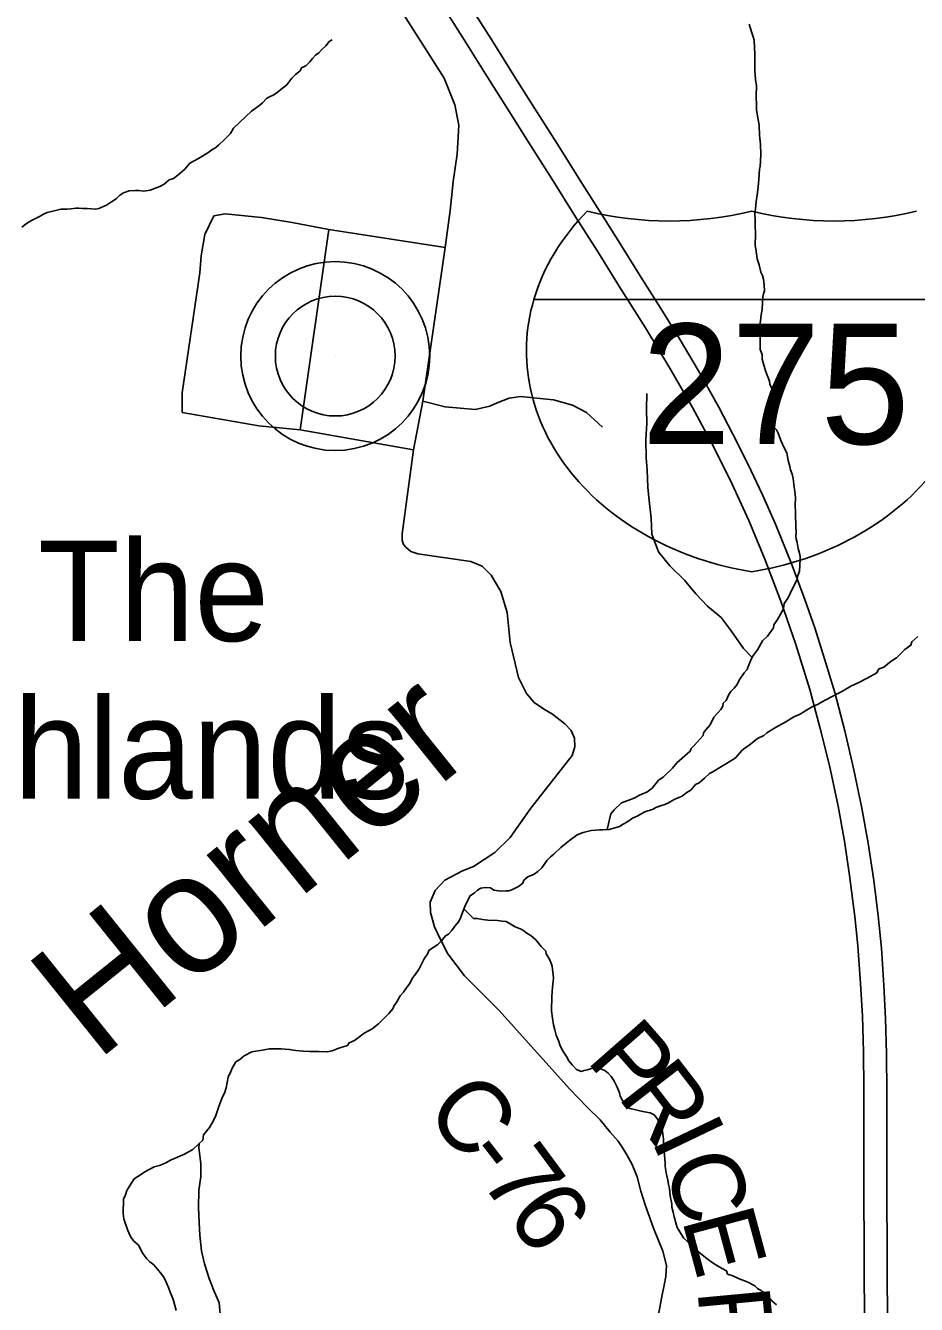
# Model space of a CAD drawing. Extents: x 44.2 to 78.2, y 4.5 to 26.5.
# Drawn here: x 50.361 to 51.062, y 23.779 to 24.786 of the extents above; entities that cross this region are included whole.
import ezdxf

# ---------------------------------------------------------------- set-up
doc = ezdxf.new("R2010")
doc.units = 0
for name, color, linetype in [('GM_X_County_Road', 7, 'Continuous'), ('GM_X_County_Road_Text', 7, 'Continuous'), ('GM_X_Interstate_Location', 7, 'Continuous'), ('GM_X_Interstate_Route', 7, 'Continuous'), ('GM_X_Interstate_Shield', 7, 'Continuous'), ('GM_X_Minor_Lake', 7, 'Continuous'), ('GM_X_Minor_River', 7, 'Continuous'), ('GM_X_Minor_River_Text', 7, 'Continuous'), ('GM_X_Township_Road', 7, 'Continuous'), ('GM_X_Unincorporated', 7, 'Continuous'), ('GM_X_Unincorporated_Location', 7, 'Continuous'), ('GM_X_Unincorporated_Text', 7, 'Continuous')]:
    doc.layers.add(name, color=color, linetype=linetype)

msp = doc.modelspace()

# ---------------------------------------------------------------- linework, layer by layer
at = {"layer": 'GM_X_County_Road'}
for points in [[(50.6961, 24.6507), (50.6974, 24.6636), (50.7006, 24.6852), (50.7018, 24.708), (50.6986, 24.724), (50.6902, 24.7449), (50.6457, 24.8153), (50.6594, 24.8273), (50.6684, 24.8359), (50.6821, 24.8482), (50.6989, 24.8631)], [(50.8591, 23.771), (50.862, 23.7867), (50.8635, 23.7942), (50.8649, 23.8011), (50.8653, 23.8097), (50.8625, 23.8211), (50.8552, 23.8392), (50.8485, 23.8574), (50.8453, 23.8683), (50.8424, 23.8795), (50.8383, 23.8893), (50.8341, 23.8969), (50.8305, 23.9029), (50.8274, 23.9077), (50.8211, 23.9147), (50.8131, 23.9244), (50.8032, 23.9342), (50.789, 23.949), (50.7336, 24.0107), (50.7063, 24.0379), (50.6933, 24.0551), (50.6872, 24.067), (50.6827, 24.0764), (50.6796, 24.0878), (50.6792, 24.096), (50.6832, 24.105), (50.6909, 24.1132), (50.7047, 24.1205), (50.7135, 24.1241), (50.7302, 24.1351), (50.7422, 24.1468), (50.7585, 24.1699), (50.7911, 24.2114), (50.7933, 24.2184), (50.7929, 24.2252), (50.7903, 24.2312), (50.7854, 24.2364), (50.7755, 24.2439), (50.7692, 24.2476), (50.7611, 24.2532), (50.7551, 24.2604), (50.7488, 24.273), (50.7422, 24.3004), (50.7399, 24.3241), (50.735, 24.3407), (50.7274, 24.3536), (50.7203, 24.3607), (50.7112, 24.3644), (50.6695, 24.3704), (50.6641, 24.3721), (50.6602, 24.3755), (50.6583, 24.3778), (50.6573, 24.3808), (50.6573, 24.3862), (50.6662, 24.4523), (50.6734, 24.4905), (50.691, 24.6116), (50.695, 24.6408), (50.6961, 24.6507)]]:
    msp.add_lwpolyline(points, dxfattribs=at)
at = {"layer": 'GM_X_Interstate_Route'}
for points in [[(50.6838, 24.8106), (50.7048, 24.7772), (50.7244, 24.7459), (50.7411, 24.7194), (50.7566, 24.6947), (50.775, 24.6657), (50.7938, 24.6359), (50.8111, 24.6088), (50.8284, 24.5806), (50.8488, 24.5483), (50.8681, 24.5166), (50.886, 24.4856), (50.9009, 24.4578), (50.9155, 24.4285), (50.9302, 24.3967), (50.9429, 24.3662), (50.9555, 24.333), (50.9674, 24.299), (50.9784, 24.2634), (50.9865, 24.2328), (50.9938, 24.2036), (51.0006, 24.1715), (51.0056, 24.144), (51.0096, 24.117), (51.0138, 24.0847), (51.0162, 24.0616), (51.0183, 24.0319), (51.0198, 24.006), (51.0205, 23.978), (51.0209, 23.9488), (51.0209, 23.9192), (51.0209, 23.8889), (51.0209, 23.8577), (51.0212, 23.8324), (51.0211, 23.8037), (51.0213, 23.7713)], [(50.7067, 24.8086), (50.7277, 24.7754), (50.7466, 24.7451), (50.7633, 24.7186), (50.7796, 24.6929), (50.7974, 24.6645), (50.8153, 24.6364), (50.8312, 24.6109), (50.8455, 24.5879), (50.8609, 24.5636), (50.8754, 24.5401), (50.8906, 24.5145), (50.9066, 24.4859), (50.9178, 24.4647), (50.9294, 24.4411), (50.9411, 24.4167), (50.9513, 24.3936), (50.9637, 24.3631), (50.9744, 24.3343), (50.9822, 24.3121), (50.99, 24.2875), (50.9979, 24.2612), (51.0058, 24.2309), (51.0131, 24.2003), (51.0194, 24.1699), (51.0243, 24.1425), (51.0287, 24.1131), (51.0322, 24.0851), (51.0347, 24.0596), (51.0365, 24.0303), (51.038, 24.0044), (51.0387, 23.9764), (51.0389, 23.9463), (51.0391, 23.9176), (51.0391, 23.8873), (51.0391, 23.8561), (51.0393, 23.8308), (51.0393, 23.8021), (51.0395, 23.7697)]]:
    msp.add_lwpolyline(points, dxfattribs=at)
at = {"layer": 'GM_X_Interstate_Shield'}
msp.add_line((51.1043, 24.5707), (50.7609, 24.5707), dxfattribs=at)
msp.add_line((51.1043, 24.5707), (50.7609, 24.5707), dxfattribs=at)
for centre, start_param, end_param in [((50.977, 24.5301), 2.47259, 2.911027), ((50.8677, 24.81), 4.415841, 5.008937), ((50.9974, 24.81), 4.415841, 5.008937), ((50.977, 24.5301), 2.911027, 4.511031), ((50.8882, 24.5301), 4.913747, 6.513751)]:
    msp.add_ellipse(centre, major_axis=(0.2219, 0), ratio=0.8, start_param=start_param, end_param=end_param, dxfattribs=at)
at = {"layer": 'GM_X_Minor_Lake'}
for points in [[(50.4687, 23.8896), (50.471, 23.8907), (50.4752, 23.8929), (50.4779, 23.8939), (50.4825, 23.8961), (50.4852, 23.8972), (50.4875, 23.8986), (50.4922, 23.9012), (50.4968, 23.9052)], [(50.4972, 23.9056), (50.497, 23.9023), (50.4987, 23.8901), (50.4985, 23.8798), (50.4971, 23.8688), (50.4968, 23.8555), (50.4974, 23.8437), (50.4979, 23.8335), (50.4992, 23.8213), (50.5016, 23.811), (50.5052, 23.7995), (50.5088, 23.7899), (50.5131, 23.7803), (50.5144, 23.7662), (50.5126, 23.756), (50.4887, 23.7154)], [(50.4791, 23.7744), (50.477, 23.7821), (50.4759, 23.7851), (50.4745, 23.7886), (50.4731, 23.7924), (50.4713, 23.7966), (50.4695, 23.8005), (50.4669, 23.804), (50.4617, 23.8102), (50.4584, 23.8125), (50.4562, 23.8149), (50.4529, 23.8191), (50.4496, 23.8257), (50.4455, 23.8292), (50.4433, 23.8326), (50.4412, 23.8373), (50.439, 23.8434), (50.438, 23.8464), (50.4373, 23.8506), (50.4376, 23.862), (50.4392, 23.8654), (50.4404, 23.8688), (50.4424, 23.8721), (50.446, 23.8781), (50.4518, 23.8817), (50.4545, 23.8836), (50.4618, 23.8875), (50.466, 23.8886), (50.4687, 23.8896)]]:
    msp.add_lwpolyline(points, dxfattribs=at)
at = {"layer": 'GM_X_Minor_River'}
for points in [[(50.9408, 24.5631), (50.9414, 24.5726), (50.9419, 24.5752), (50.9427, 24.5775), (50.9424, 24.582), (50.9418, 24.5866), (50.9411, 24.5897), (50.9397, 24.5923), (50.9383, 24.5981), (50.9369, 24.6027), (50.9359, 24.6107), (50.9353, 24.6133), (50.9355, 24.6224), (50.9353, 24.6289), (50.9354, 24.6331), (50.9351, 24.6387), (50.9356, 24.6421), (50.9361, 24.6478), (50.9366, 24.6512), (50.9371, 24.655), (50.9376, 24.6595), (50.9381, 24.6652), (50.9387, 24.6732), (50.9391, 24.6754), (50.9396, 24.68), (50.9397, 24.6849), (50.9396, 24.6929), (50.9386, 24.7001), (50.9384, 24.7081), (50.9374, 24.7138), (50.9364, 24.7199), (50.9362, 24.7237), (50.936, 24.7305), (50.9362, 24.7396), (50.9355, 24.7438), (50.935, 24.7514), (50.9351, 24.7567), (50.9349, 24.7639), (50.9344, 24.775), (50.9337, 24.7776), (50.933, 24.7799), (50.9313, 24.7849), (50.9306, 24.7876)], [(50.3575, 24.6277), (50.3622, 24.631), (50.3653, 24.6328), (50.3714, 24.6361), (50.3753, 24.6382), (50.3776, 24.6393), (50.381, 24.64), (50.3883, 24.6417), (50.3932, 24.6419), (50.3963, 24.6422), (50.4001, 24.6425), (50.4024, 24.6425), (50.4054, 24.6424), (50.4092, 24.6423), (50.4156, 24.6417), (50.4183, 24.6424), (50.4244, 24.6449), (50.4283, 24.6475), (50.4318, 24.65), (50.4345, 24.6526), (50.4376, 24.6548), (50.4422, 24.6562), (50.4471, 24.6565), (50.4498, 24.6564), (50.4536, 24.6559), (50.4586, 24.6569), (50.462, 24.658), (50.4662, 24.6598), (50.4697, 24.6616), (50.4736, 24.6649), (50.477, 24.6659), (50.4805, 24.6685), (50.4859, 24.6733), (50.4899, 24.6781), (50.4968, 24.6817), (50.5014, 24.6846), (50.5041, 24.6861), (50.5072, 24.6886), (50.5103, 24.6905), (50.5126, 24.6923), (50.5173, 24.6967), (50.522, 24.7015), (50.5244, 24.7057), (50.5384, 24.7189), (50.545, 24.7237), (50.5473, 24.7255), (50.5504, 24.7289), (50.5527, 24.7303), (50.5562, 24.7318), (50.5589, 24.734), (50.5639, 24.738), (50.5663, 24.7398), (50.5702, 24.745), (50.5733, 24.748), (50.5768, 24.7509), (50.578, 24.7532), (50.5814, 24.7546), (50.5846, 24.7579), (50.5865, 24.7605), (50.5889, 24.7631), (50.5916, 24.765), (50.5939, 24.7676), (50.597, 24.7705), (50.5998, 24.7739), (50.6021, 24.7753)], [(50.8187, 24.1531), (50.8217, 24.1656), (50.8241, 24.1686), (50.8299, 24.1741), (50.8349, 24.1759), (50.8406, 24.178), (50.8441, 24.1802), (50.8464, 24.1813), (50.8499, 24.1827), (50.8541, 24.1856), (50.8573, 24.1897), (50.8592, 24.192), (50.8627, 24.1945), (50.8701, 24.2015), (50.8736, 24.2056), (50.8841, 24.2148), (50.8849, 24.2171), (50.8873, 24.2193), (50.8943, 24.2271), (50.8947, 24.2293), (50.8963, 24.2316), (50.8998, 24.2357), (50.9026, 24.2417), (50.9058, 24.245), (50.9081, 24.2476), (50.9097, 24.2502), (50.9101, 24.2528), (50.9125, 24.2547), (50.9145, 24.2596), (50.9161, 24.2618), (50.9188, 24.2644), (50.9211, 24.2673), (50.9227, 24.2707), (50.9267, 24.2767), (50.929, 24.2793), (50.9303, 24.283), (50.9327, 24.2883), (50.9339, 24.2905), (50.937, 24.2946), (50.941, 24.3017), (50.9449, 24.3054), (50.9496, 24.3121), (50.9501, 24.3144), (50.9524, 24.3177), (50.9536, 24.32), (50.9576, 24.3271), (50.9581, 24.3312), (50.9612, 24.3357), (50.9628, 24.3391), (50.9684, 24.3503), (50.9689, 24.3533), (50.9701, 24.3567), (50.9707, 24.3658), (50.9708, 24.3681), (50.9701, 24.3708), (50.9691, 24.3746), (50.9684, 24.3792), (50.9677, 24.3822), (50.9674, 24.3845), (50.9675, 24.3868), (50.9672, 24.3925), (50.9673, 24.3955), (50.967, 24.3978), (50.9671, 24.4023), (50.9669, 24.4092), (50.967, 24.4141), (50.9667, 24.4175), (50.9664, 24.4198), (50.9661, 24.4228), (50.9651, 24.4297), (50.9645, 24.4331), (50.963, 24.4366), (50.9627, 24.4392), (50.9613, 24.4438), (50.9603, 24.4499), (50.9585, 24.4534), (50.9556, 24.4595), (50.9535, 24.4653), (50.9521, 24.468), (50.9495, 24.4707), (50.9481, 24.476), (50.947, 24.4791), (50.9483, 24.4851), (50.9488, 24.4874), (50.9492, 24.49), (50.95, 24.4931), (50.9501, 24.4961), (50.9494, 24.4988), (50.948, 24.5015), (50.9469, 24.5041), (50.9466, 24.5064), (50.9434, 24.5145), (50.9409, 24.5236), (50.9407, 24.5274), (50.9392, 24.5313), (50.9391, 24.5393), (50.9392, 24.5427), (50.9388, 24.5453), (50.9389, 24.5495), (50.9399, 24.5586), (50.9408, 24.5631)], [(50.9329, 24.2887), (50.926, 24.2958), (50.9164, 24.3096), (50.9086, 24.3201), (50.8978, 24.329), (50.8885, 24.3387), (50.8796, 24.3495), (50.8681, 24.3608), (50.8592, 24.372), (50.8538, 24.3858), (50.8533, 24.3983), (50.8517, 24.4124), (50.8507, 24.4227), (50.8503, 24.4364), (50.8493, 24.4459), (50.8492, 24.46), (50.8499, 24.4733), (50.8497, 24.4839), (50.85, 24.4965)], [(50.9187, 24.2089), (50.9204, 24.2101), (50.9248, 24.2153), (50.9275, 24.2175), (50.9302, 24.2193), (50.9372, 24.2248), (50.9422, 24.2273), (50.9445, 24.2292), (50.9514, 24.2336), (50.9595, 24.2379), (50.9657, 24.2419), (50.9707, 24.244), (50.973, 24.2455), (50.9796, 24.2495), (50.9849, 24.252), (50.9876, 24.2535), (50.9953, 24.2578), (51.0015, 24.2607), (51.0042, 24.2621), (51.0107, 24.2661), (51.0169, 24.269), (51.0234, 24.2723), (51.0311, 24.2766), (51.0324, 24.2796), (51.0366, 24.281), (51.0424, 24.2858), (51.0466, 24.2883), (51.0533, 24.295), (51.0579, 24.2983), (51.0587, 24.3009), (51.0634, 24.3053)], [(50.8283, 24.1556), (50.8314, 24.1574), (50.8341, 24.1589), (50.8387, 24.1622), (50.8422, 24.1636), (50.8483, 24.1672), (50.8548, 24.1693), (50.8571, 24.1704), (50.8606, 24.1718), (50.864, 24.1729), (50.8671, 24.1743), (50.8714, 24.1769), (50.8752, 24.1783), (50.8779, 24.1793), (50.8806, 24.1819), (50.8849, 24.1845), (50.8884, 24.1885), (50.8911, 24.19), (50.8953, 24.1937), (50.8992, 24.1974), (50.9015, 24.1984), (50.9187, 24.2089)], [(50.4968, 23.9052), (50.5003, 23.9085), (50.5008, 23.9127), (50.5055, 23.9183), (50.5083, 23.9235), (50.5103, 23.928), (50.5119, 23.9325), (50.5128, 23.9351), (50.5156, 23.9426), (50.5172, 23.9456), (50.5185, 23.9498), (50.5202, 23.9581), (50.5222, 23.9626), (50.5234, 23.9652), (50.5262, 23.9701), (50.5293, 23.9719), (50.5328, 23.9748), (50.5389, 23.9781), (50.5485, 23.9797), (50.5527, 23.9804), (50.5618, 23.9805), (50.5682, 23.98), (50.5735, 23.9791), (50.5792, 23.9785), (50.5845, 23.9784), (50.5913, 23.9782), (50.5982, 23.978), (50.602, 23.9787), (50.6074, 23.9808), (50.6142, 23.9829), (50.6154, 23.9852), (50.6197, 23.987), (50.6274, 23.9928), (50.6336, 23.9961), (50.6386, 24.0001), (50.6468, 24.0082), (50.6499, 24.012), (50.6508, 24.0146), (50.6527, 24.0168), (50.6555, 24.0221), (50.6582, 24.025), (50.6606, 24.0284), (50.6634, 24.0325), (50.6654, 24.0362), (50.6673, 24.0384), (50.6705, 24.0433), (50.6725, 24.047), (50.6749, 24.0519), (50.6772, 24.0549), (50.6781, 24.0579), (50.6808, 24.0597), (50.6854, 24.0626), (50.6881, 24.0656), (50.6913, 24.0693), (50.6936, 24.0707), (50.6963, 24.0737), (50.6987, 24.0771), (50.7018, 24.0808), (50.7034, 24.0841), (50.7055, 24.0898), (50.7071, 24.0939), (50.7107, 24.101), (50.7142, 24.1032), (50.7165, 24.1054), (50.7192, 24.1069), (50.7226, 24.1075), (50.7268, 24.1071), (50.7294, 24.1055), (50.7351, 24.1046), (50.7389, 24.1048), (50.7412, 24.1048), (50.7442, 24.1058), (50.7488, 24.1084), (50.7523, 24.1109), (50.7531, 24.1132), (50.7563, 24.1158), (50.7612, 24.1179), (50.764, 24.1201), (50.7671, 24.1231), (50.7714, 24.129), (50.7741, 24.1316), (50.7768, 24.1338), (50.7823, 24.139), (50.7865, 24.1423), (50.7889, 24.1445), (50.7951, 24.1489), (50.7997, 24.1507), (50.8062, 24.1524), (50.8096, 24.1527), (50.8126, 24.153), (50.8149, 24.1529), (50.8202, 24.1532), (50.8283, 24.1556)], [(50.7058, 24.0908), (50.7133, 24.0831), (50.7163, 24.083), (50.7205, 24.0822), (50.7246, 24.0817), (50.7322, 24.0815), (50.736, 24.081), (50.739, 24.0806), (50.7424, 24.0789), (50.7461, 24.0766), (50.7514, 24.0745), (50.7563, 24.071), (50.7585, 24.0698), (50.7626, 24.0663), (50.7666, 24.0609), (50.7703, 24.0574), (50.7707, 24.0551), (50.7736, 24.0504), (50.7754, 24.0455), (50.7763, 24.0363), (50.7762, 24.0337), (50.7757, 24.0291), (50.7751, 24.0216), (50.7748, 24.0102), (50.7755, 24.0045), (50.7765, 23.9992), (50.7775, 23.9953), (50.7785, 23.9911), (50.7807, 23.9861), (50.7814, 23.9835), (50.7835, 23.9792), (50.7872, 23.9735), (50.7883, 23.9712), (50.7912, 23.9677), (50.7946, 23.9642), (50.7983, 23.9626), (50.8006, 23.9632), (50.8033, 23.9639), (50.8056, 23.9646), (50.8086, 23.9653), (50.8113, 23.9652), (50.8139, 23.9644), (50.8169, 23.9632), (50.8196, 23.9612), (50.8218, 23.9585), (50.824, 23.9554), (50.8265, 23.9501), (50.8283, 23.9458), (50.829, 23.9432), (50.8308, 23.9397), (50.8334, 23.9366), (50.8352, 23.9339), (50.8375, 23.9331), (50.8401, 23.9326), (50.8454, 23.9314), (50.848, 23.9309), (50.8526, 23.93), (50.8556, 23.9284), (50.8578, 23.9257), (50.8618, 23.9195), (50.8624, 23.9154), (50.8631, 23.9093), (50.863, 23.9059), (50.8636, 23.8994), (50.8645, 23.8906), (50.8644, 23.8876), (50.8654, 23.8815), (50.8664, 23.8769), (50.8671, 23.8735), (50.8678, 23.8705), (50.8681, 23.8674), (50.8684, 23.8647), (50.8697, 23.8583), (50.8697, 23.8556), (50.8707, 23.8518), (50.8714, 23.848), (50.8728, 23.8434), (50.8738, 23.8396), (50.8789, 23.8315), (50.8826, 23.828), (50.8852, 23.8249), (50.8949, 23.817), (50.9005, 23.8127), (50.9042, 23.8103), (50.9087, 23.8076), (50.9128, 23.8056), (50.9135, 23.8029), (50.9177, 23.8016), (50.9226, 23.7992), (50.9289, 23.7968), (50.9349, 23.7936), (50.9372, 23.7916), (50.9402, 23.7897), (50.945, 23.7857), (50.9483, 23.7819), (50.952, 23.7787)]]:
    msp.add_lwpolyline(points, dxfattribs=at)
at = {"layer": 'GM_X_Township_Road'}
msp.add_line((50.5768, 24.468), (50.5995, 24.6258), dxfattribs=at)
for points in [[(50.5089, 24.6365), (50.5018, 24.6219), (50.4989, 24.6051), (50.4979, 24.5918), (50.4838, 24.4972), (50.4838, 24.4816)], [(50.691, 24.6116), (50.5995, 24.6258), (50.5705, 24.6313), (50.5465, 24.6352), (50.5177, 24.6381), (50.5089, 24.6365)], [(50.6734, 24.4905), (50.691, 24.4861), (50.7146, 24.484), (50.7263, 24.4867), (50.7321, 24.4893), (50.7415, 24.4929), (50.7503, 24.4943), (50.7764, 24.4915), (50.7915, 24.4875), (50.8023, 24.4817), (50.8149, 24.4701)], [(50.6662, 24.4523), (50.5768, 24.468), (50.5444, 24.4711), (50.4838, 24.4816)]]:
    msp.add_lwpolyline(points, dxfattribs=at)
at = {"layer": 'GM_X_Unincorporated'}
for radius in [0.0744, 0.0472]:
    msp.add_circle((50.6045, 24.5261), radius, dxfattribs=at)
at = {"layer": 'GM_X_Unincorporated_Location'}
msp.add_line((50.6045, 24.5261), (50.6045, 24.5261), dxfattribs=at)

# ---------------------------------------------------------------- texts
at = {"layer": 'GM_X_County_Road_Text'}
for s, rotation, p in [('P', 311.2682, (50.8013, 23.9712)), ('R', 307.6778, (50.826, 23.9431)), ('C', 310.5052, (50.6736, 23.9305)), ('I', 295.5946, (50.8528, 23.9089)), ('-', 307.9613, (50.7035, 23.8955)), ('7', 306.4754, (50.7176, 23.8774)), ('C', 289.1471, (50.8623, 23.8894)), ('6', 305.548, (50.7383, 23.8495)), ('E', 285.0871, (50.8773, 23.8463)), ('R', 275.3665, (50.8897, 23.7904))]:
    msp.add_text(s, height=0.0568, rotation=rotation, dxfattribs=at).set_placement(p)
at = {"layer": 'GM_X_Interstate_Location'}
for s in ['-', '.', ',']:
    msp.add_text(s, height=0.000189, dxfattribs=at).set_placement((50.9326, 24.504))
msp.add_text('275', height=0.000189, rotation=0, dxfattribs=at).set_placement((50.8747, 24.4648))
at = {"layer": 'GM_X_Interstate_Shield'}
msp.add_text('275', height=0.0947, dxfattribs=at).set_placement((50.8458, 24.4568))
at = {"layer": 'GM_X_Minor_River_Text'}
msp.add_text('Horner', height=0.09469, rotation=38.8184, dxfattribs=at).set_placement((50.416, 23.9696))
at = {"layer": 'GM_X_Unincorporated_Text'}
for s, p in [('The', (50.3703, 24.3016)), ('Highlands', (50.1928, 24.1774))]:
    msp.add_text(s, height=0.07898, rotation=0, dxfattribs=at).set_placement(p)

doc.saveas('drawing.dxf')
